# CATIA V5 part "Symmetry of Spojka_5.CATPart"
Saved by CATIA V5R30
Part number: Symmetry of Spojka_5
Bounding box of the stored display mesh (mm): x -8.66 to 8.66, y -7.5 to 7.5, z -9 to 17
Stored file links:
  E:\Bakalarka\Model\Forma_v7\Symmetry of Spojka_5.CATPart
  E:\Bakalarka\Model\Forma_v7\Spojka_1.CATPart
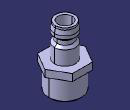
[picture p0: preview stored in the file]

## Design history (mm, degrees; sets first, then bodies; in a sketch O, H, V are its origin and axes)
Body1 (main body)
  Body2 "Body from original PartBody"
    Solid1: linked copy from another document
  Assemble1: tool Body2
